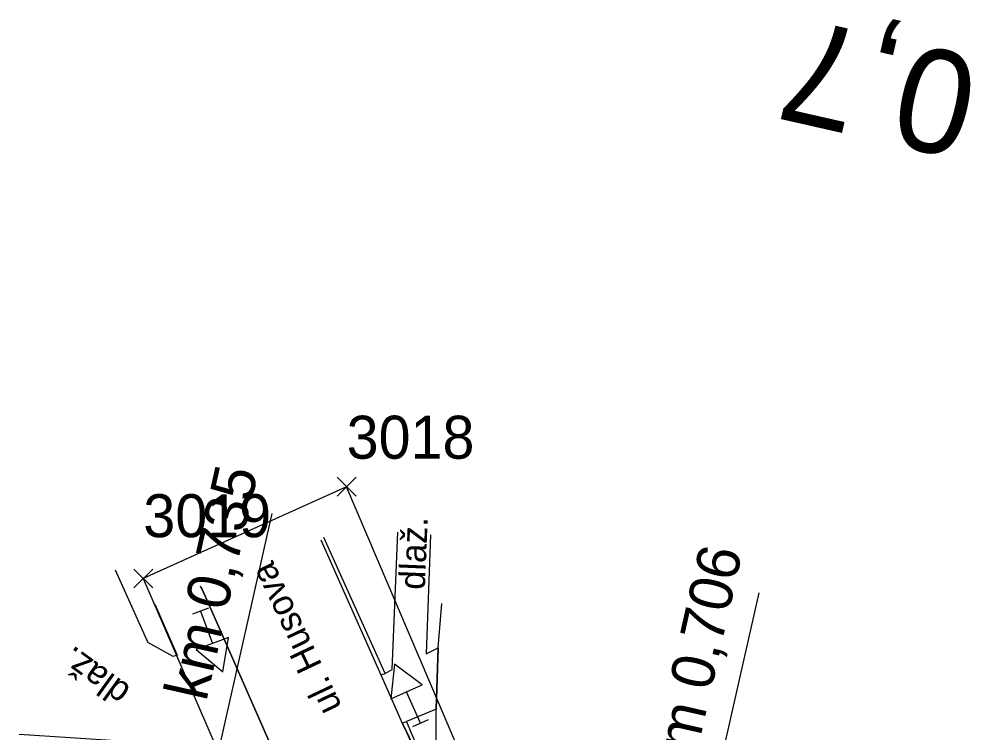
# Model space of a CAD drawing. Extents: x -738085 to -734426, y -1122197 to -1119748.
# Drawn here: x -734716.3 to -734660.8, y -1120185 to -1120143.5 of the extents above; entities that cross this region are included whole.
import ezdxf

# ---------------------------------------------------------------- set-up
doc = ezdxf.new("R2010")
doc.units = 0
for name, color, linetype in [('Dočasný zábor - do 1 roku', 7, 'Continuous'), ('Vrstva 16', 7, 'Continuous'), ('Vrstva 3', 7, 'Continuous'), ('Vrstva 51', 7, 'Continuous'), ('Vrstva 60', 7, 'Continuous'), ('Vrstva 7', 7, 'Continuous')]:
    doc.layers.add(name, color=color, linetype=linetype)

msp = doc.modelspace()

# ---------------------------------------------------------------- linework, layer by layer
at = {"layer": 'Dočasný zábor - do 1 roku'}
for p, q in [((-734697.213, -1120170.677), (-734709.047, -1120176.015)), ((-734688.3, -1120191.56), (-734697.213, -1120170.677)), ((-734709.047, -1120176.015), (-734701.56, -1120193.32))]:
    msp.add_line(p, q, dxfattribs=at)
at = {"layer": 'Vrstva 16'}
for p, q in [((-734710.677, -1120175.51), (-734708.779, -1120179.74)), ((-734691.887, -1120180.057), (-734691.681, -1120177.466)), ((-734695.23, -1120181.618), (-734693.983, -1120184.429)), ((-734693.983, -1120184.429), (-734693.738, -1120184.328))]:
    msp.add_line(p, q, dxfattribs=at)
for points in [[(-734698.706, -1120173.764), (-734695.23, -1120181.618), (-734694.971, -1120181.533), (-734698.533, -1120173.639)], [(-734695.23, -1120181.618), (-734694.971, -1120181.533), (-734694.56, -1120181.305), (-734694.228, -1120173.314)], [(-734692.324, -1120173.479), (-734692.585, -1120180.404), (-734691.887, -1120180.057), (-734692.012, -1120183.607), (-734693.738, -1120184.328)], [(-734716.277, -1120185.064), (-734707.365, -1120185.654), (-734705.654, -1120185.987), (-734704.28, -1120186.791), (-734703.295, -1120189.048), (-734700.649, -1120196.031), (-734698.09, -1120195.452), (-734697.927, -1120195.313), (-734697.93, -1120195.257), (-734698.174, -1120195.122), (-734700.415, -1120188.521), (-734700.884, -1120187.404), (-734704.979, -1120178.091), (-734705.423, -1120177.081), (-734705.712, -1120176.457)], [(-734705.673, -1120176.523), (-734705.425, -1120177.079), (-734704.979, -1120178.091), (-734705.423, -1120177.081), (-734705.712, -1120176.457)], [(-734708.384, -1120177.514), (-734707.067, -1120180.47), (-734707.303, -1120180.545), (-734708.779, -1120179.74)], [(-734693.983, -1120184.429), (-734693.706, -1120184.991), (-734691.09, -1120190.87), (-734689.481, -1120193.204), (-734687.051, -1120194.004), (-734685.594, -1120191.915), (-734685.657, -1120188.975), (-734690.021, -1120190.906), (-734692.007, -1120186.315), (-734692.012, -1120183.607), (-734691.887, -1120180.057), (-734691.681, -1120177.463)], [(-734693.983, -1120184.429), (-734693.673, -1120185.028), (-734691.091, -1120190.868), (-734689.48, -1120193.207), (-734687.051, -1120194.004), (-734685.605, -1120191.915), (-734685.658, -1120188.976), (-734690.023, -1120190.9), (-734692.008, -1120186.313), (-734692.012, -1120183.607)], [(-734693.983, -1120184.429), (-734693.738, -1120184.328), (-734693.487, -1120184.951), (-734690.892, -1120190.781), (-734689.361, -1120193.039), (-734687.053, -1120193.814), (-734685.709, -1120191.874), (-734685.703, -1120189.123), (-734690.085, -1120191.06)]]:
    msp.add_lwpolyline(points, dxfattribs=at)
at = {"layer": 'Vrstva 3'}
for p, q in [((-734701.56, -1120172.241), (-734707.734, -1120199.476)), ((-734673.222, -1120176.84), (-734679.781, -1120205.8))]:
    msp.add_line(p, q, dxfattribs=at)
at = {"layer": 'Vrstva 51'}
for p, q in [((-734705.249, -1120177.746), (-734706.187, -1120178.092)), ((-734693.366, -1120184.631), (-734692.452, -1120184.223))]:
    msp.add_line(p, q, dxfattribs=at)
for points in [[(-734698.706, -1120173.764), (-734695.23, -1120181.618), (-734693.983, -1120184.429), (-734693.706, -1120184.991), (-734691.09, -1120190.87), (-734689.481, -1120193.204), (-734687.051, -1120194.004), (-734685.594, -1120191.915), (-734685.657, -1120188.975)], [(-734704.979, -1120178.091), (-734705.425, -1120177.079), (-734705.673, -1120176.523)], [(-734692.007, -1120186.315), (-734692.012, -1120183.607), (-734691.887, -1120180.057), (-734691.681, -1120177.463)], [(-734705.718, -1120177.919), (-734705.027, -1120179.796), (-734705.965, -1120180.141), (-734704.422, -1120181.438), (-734704.088, -1120179.45), (-734705.027, -1120179.796)], [(-734704.979, -1120178.091), (-734700.884, -1120187.404), (-734700.409, -1120188.524), (-734698.04, -1120194.915)], [(-734692.909, -1120184.427), (-734693.724, -1120182.601), (-734692.811, -1120182.193), (-734694.437, -1120181.002), (-734694.637, -1120183.008), (-734693.724, -1120182.601)]]:
    msp.add_lwpolyline(points, dxfattribs=at)
at = {"layer": 'Vrstva 60'}
for p, q in [((-734696.763, -1120171.127), (-734697.763, -1120170.127)), ((-734696.763, -1120170.227), (-734697.763, -1120171.227)), ((-734697.663, -1120171.127), (-734696.663, -1120170.127)), ((-734697.663, -1120170.227), (-734696.663, -1120171.227)), ((-734697.213, -1120170.677), (-734697.213, -1120170.677)), ((-734708.597, -1120176.465), (-734709.597, -1120175.465)), ((-734708.597, -1120175.565), (-734709.597, -1120176.565)), ((-734709.497, -1120176.465), (-734708.497, -1120175.465)), ((-734709.497, -1120175.565), (-734708.497, -1120176.565)), ((-734709.047, -1120176.015), (-734709.047, -1120176.015))]:
    msp.add_line(p, q, dxfattribs=at)

# ---------------------------------------------------------------- texts
at = {"layer": 'Vrstva 16'}
for rotation, p in [(87.6209, (-734692.665, -1120176.688)), (144.1658, (-734709.704, -1120182.349))]:
    msp.add_text('dlaž.', height=1.5, rotation=rotation, dxfattribs=at).set_placement(p)
at = {"layer": 'Vrstva 3'}
for s, rotation, p in [('km 0,735', 77.2663, (-734705.386, -1120183.216)), ('km 0,706', 77.2383, (-734677.207, -1120187.86))]:
    msp.add_text(s, height=2.5, rotation=rotation, dxfattribs=at).set_placement(p)
at = {"layer": 'Vrstva 51'}
msp.add_text('ul. Husova', height=1.5, rotation=115.4117, dxfattribs=at).set_placement((-734697.465, -1120183.475))
at = {"layer": 'Vrstva 60'}
for s, p in [('3018', (-734697.213, -1120169.049)), ('3019', (-734709.047, -1120173.614))]:
    msp.add_text(s, height=2.5, dxfattribs=at).set_placement(p)
at = {"layer": 'Vrstva 7'}
msp.add_text('0,7', height=6, rotation=167.2383, dxfattribs=at).set_placement((-734660.13, -1120145.82))
msp.add_text('0,7', height=6, rotation=167.2383, dxfattribs=at).set_placement((-734660.13, -1120145.82))

doc.saveas('drawing.dxf')
